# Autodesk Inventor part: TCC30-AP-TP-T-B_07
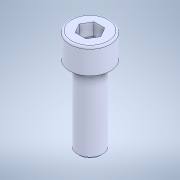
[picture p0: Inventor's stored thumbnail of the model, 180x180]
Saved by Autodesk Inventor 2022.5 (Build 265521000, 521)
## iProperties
Created: 2023-09
Part Number: TCC30-AP-TP-T-B_07
Material: 一般
Document SubType Name: Modeling
Designer: ImaoCorp
Density: 1 g/cm^3
Appearance: 既定
Author: ImaoCorp
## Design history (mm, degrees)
feature "TCC30-AP-TP-T-B_07"
node "ソリッド1"
